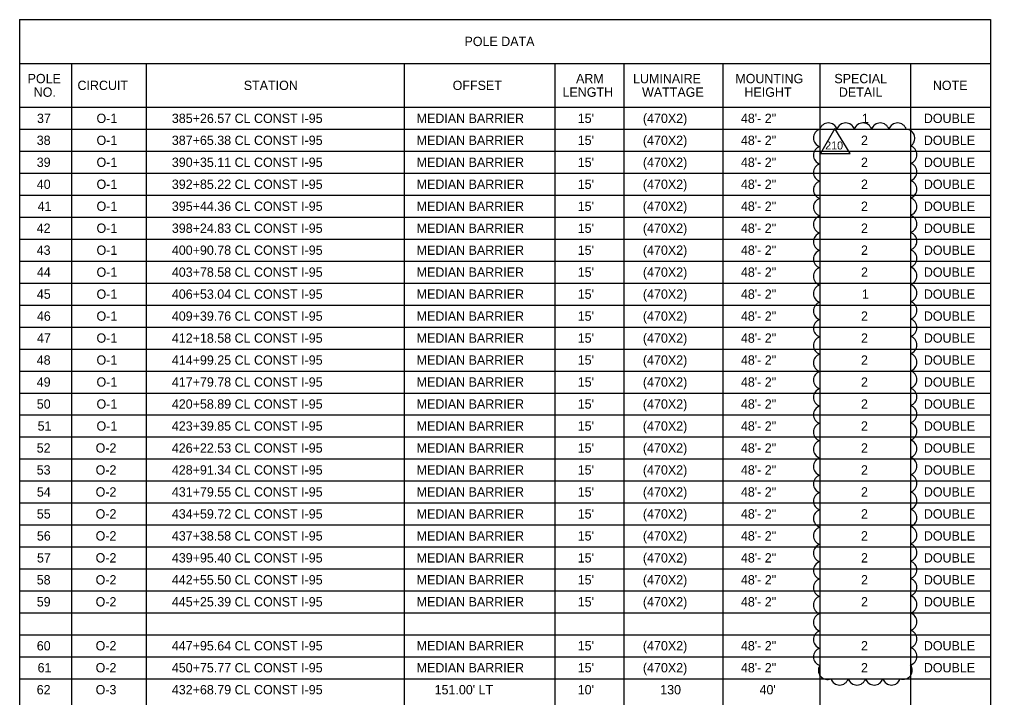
# Model space of a CAD drawing. Extents: x -816.7 to -727.6, y -2197.9 to -2187.8.
# Drawn here: x -808.11 to -800.82, y -2193.19 to -2188.1 of the extents above; entities that cross this region are included whole.
import ezdxf

# ---------------------------------------------------------------- set-up
doc = ezdxf.new("R2010")
doc.units = 0
for name, color, linetype in [('ClipBorder_dp', 7, 'Continuous'), ('MatchLines_dp', 7, 'Continuous'), ('NorthArw_dp', 7, 'Continuous'), ('PlotBorder_dp', 7, 'Continuous'), ('Scale_dp', 7, 'Continuous')]:
    doc.layers.add(name, color=color, linetype=linetype)

msp = doc.modelspace()

# ---------------------------------------------------------------- linework, layer by layer
at = {"layer": 'MatchLines_dp'}
for p, q in [((-808.1136, -2188.7573), (-807.1611, -2188.7573)), ((-804.0936, -2188.7573), (-800.8236, -2188.7573)), ((-808.1136, -2188.9223), (-807.1611, -2188.9223)), ((-808.1136, -2188.9223), (-800.8236, -2188.9223)), ((-805.2261, -2188.9223), (-800.8236, -2188.9223)), ((-808.1136, -2189.0873), (-800.8236, -2189.0873)), ((-808.1136, -2189.0873), (-800.8236, -2189.0873)), ((-808.1136, -2189.2523), (-800.8236, -2189.2523)), ((-808.1136, -2189.2523), (-800.8236, -2189.2523)), ((-808.1136, -2189.4173), (-800.8236, -2189.4173)), ((-808.1136, -2189.4173), (-800.8236, -2189.4173)), ((-808.1136, -2189.5823), (-800.8236, -2189.5823)), ((-808.1136, -2189.5823), (-800.8236, -2189.5823)), ((-808.1136, -2189.7473), (-800.8236, -2189.7473)), ((-808.1136, -2189.7473), (-800.8236, -2189.7473)), ((-808.1136, -2189.9123), (-800.8236, -2189.9123)), ((-808.1136, -2189.9123), (-800.8236, -2189.9123)), ((-808.1136, -2190.0773), (-800.8236, -2190.0773)), ((-808.1136, -2190.0773), (-800.8236, -2190.0773)), ((-808.1136, -2190.2423), (-800.8236, -2190.2423)), ((-808.1136, -2190.2423), (-800.8236, -2190.2423)), ((-808.1136, -2190.4073), (-800.8236, -2190.4073)), ((-808.1136, -2190.4073), (-800.8236, -2190.4073)), ((-808.1136, -2190.5723), (-807.1611, -2190.5723)), ((-808.1136, -2190.5723), (-800.8236, -2190.5723)), ((-804.0936, -2190.5723), (-800.8236, -2190.5723)), ((-808.1136, -2190.7373), (-807.7236, -2190.7373)), ((-808.1136, -2190.7373), (-800.8236, -2190.7373)), ((-807.1611, -2190.7373), (-805.2261, -2190.7373)), ((-803.5761, -2190.7373), (-802.1061, -2190.7373)), ((-808.1136, -2190.9023), (-800.8236, -2190.9023)), ((-808.1136, -2190.9023), (-800.8236, -2190.9023)), ((-808.1136, -2191.0673), (-807.7236, -2191.0673)), ((-808.1136, -2191.0673), (-800.8236, -2191.0673)), ((-802.8336, -2191.0673), (-802.1061, -2191.0673)), ((-808.1136, -2191.2323), (-807.7236, -2191.2323)), ((-808.1136, -2191.2323), (-800.8236, -2191.2323)), ((-802.8336, -2191.2323), (-802.1061, -2191.2323)), ((-808.1136, -2191.3973), (-800.8236, -2191.3973)), ((-808.1136, -2191.3973), (-800.8236, -2191.3973)), ((-808.1136, -2191.5623), (-800.8236, -2191.5623)), ((-808.1136, -2191.5623), (-800.8236, -2191.5623)), ((-808.1136, -2191.7273), (-800.8236, -2191.7273)), ((-808.1136, -2191.7273), (-800.8236, -2191.7273)), ((-808.1136, -2191.8923), (-800.8236, -2191.8923)), ((-808.1136, -2191.8923), (-800.8236, -2191.8923)), ((-808.1136, -2192.0573), (-800.8236, -2192.0573)), ((-808.1136, -2192.0573), (-800.8236, -2192.0573)), ((-808.1136, -2192.2223), (-800.8236, -2192.2223)), ((-808.1136, -2192.2223), (-800.8236, -2192.2223)), ((-808.1136, -2192.3873), (-800.8236, -2192.3873)), ((-808.1136, -2192.3873), (-800.8236, -2192.3873)), ((-808.1136, -2192.5523), (-800.8236, -2192.5523)), ((-808.1136, -2192.5523), (-800.8236, -2192.5523)), ((-808.1136, -2192.7173), (-800.8236, -2192.7173)), ((-808.1136, -2192.7173), (-800.8236, -2192.7173)), ((-808.1136, -2192.8823), (-800.8236, -2192.8823)), ((-808.1136, -2192.8823), (-800.8236, -2192.8823)), ((-808.1136, -2193.0473), (-800.8236, -2193.0473)), ((-808.1136, -2193.0473), (-800.8236, -2193.0473))]:
    msp.add_line(p, q, dxfattribs=at)
at = {"layer": 'NorthArw_dp'}
for p, q in [((-808.1136, -2188.0973), (-800.8236, -2188.0973)), ((-808.1136, -2188.0973), (-808.1136, -2194.6973)), ((-800.8236, -2188.0973), (-800.8236, -2194.6973)), ((-808.1136, -2188.4273), (-800.8236, -2188.4273)), ((-808.1136, -2188.4273), (-800.8236, -2188.4273))]:
    msp.add_line(p, q, dxfattribs=at)
at = {"layer": 'PlotBorder_dp'}
msp.add_lwpolyline([(-801.9916, -2188.9159), (-802.0993, -2189.1039), (-801.8787, -2189.1039)], close=True, dxfattribs=at)
for centre, radius, start, end in [((-802.0411, -2188.9427), 0.0681, 17.5, 162.5), ((-801.9113, -2188.9427), 0.0681, 17.5, 162.5), ((-801.7814, -2188.9427), 0.0681, 17.5, 162.5), ((-801.6515, -2188.9427), 0.0681, 17.5, 162.5), ((-801.5216, -2188.9427), 0.0681, 17.5, 162.5), ((-802.0856, -2188.9872), 0.0681, 107.5, 252.5), ((-801.4599, -2188.9903), 0.0681, 302.28004, 87.28004), ((-802.0856, -2189.1171), 0.0681, 107.5, 252.5), ((-801.4441, -2189.1128), 0.0681, 287.5, 72.5), ((-802.0856, -2189.2469), 0.0681, 107.5, 252.5), ((-801.4441, -2189.2426), 0.0681, 287.5, 72.5), ((-802.0856, -2189.3768), 0.0681, 107.5, 252.5), ((-801.4441, -2189.3725), 0.0681, 287.5, 72.5), ((-802.0856, -2189.5067), 0.0681, 107.5, 252.5), ((-801.4441, -2189.5024), 0.0681, 287.5, 72.5), ((-802.0856, -2189.6366), 0.0681, 107.5, 252.5), ((-801.4441, -2189.6323), 0.0681, 287.5, 72.5), ((-801.4441, -2189.7621), 0.0681, 287.5, 72.5), ((-802.0856, -2189.7664), 0.0681, 107.5, 252.5), ((-802.0856, -2189.8963), 0.0681, 107.5, 252.5), ((-801.4441, -2189.892), 0.0681, 287.5, 72.5), ((-802.0856, -2190.0262), 0.0681, 107.5, 252.5), ((-801.4441, -2190.0219), 0.0681, 287.5, 72.5), ((-802.0856, -2190.1561), 0.0681, 107.5, 252.5), ((-801.4441, -2190.1518), 0.0681, 287.5, 72.5), ((-802.0856, -2190.2859), 0.0681, 107.5, 252.5), ((-801.4441, -2190.2816), 0.0681, 287.5, 72.5), ((-802.0856, -2190.4158), 0.0681, 107.5, 252.5), ((-801.4441, -2190.4115), 0.0681, 287.5, 72.5), ((-802.0856, -2190.5457), 0.0681, 107.5, 252.5), ((-801.4441, -2190.5414), 0.0681, 287.5, 72.5), ((-802.0856, -2190.6756), 0.0681, 107.5, 252.5), ((-801.4441, -2190.6713), 0.0681, 287.5, 72.5), ((-802.0856, -2190.8054), 0.0681, 107.5, 252.5), ((-801.4441, -2190.8011), 0.0681, 287.5, 72.5), ((-802.0856, -2190.9353), 0.0681, 107.5, 252.5), ((-801.4441, -2190.931), 0.0681, 287.5, 72.5), ((-802.0856, -2191.0652), 0.0681, 107.5, 252.5), ((-801.4441, -2191.0609), 0.0681, 287.5, 72.5), ((-802.0856, -2191.1951), 0.0681, 107.5, 252.5), ((-801.4441, -2191.1908), 0.0681, 287.5, 72.5), ((-802.0856, -2191.3249), 0.0681, 107.5, 252.5), ((-801.4441, -2191.3206), 0.0681, 287.5, 72.5), ((-802.0856, -2191.4548), 0.0681, 107.5, 252.5), ((-801.4441, -2191.4505), 0.0681, 287.5, 72.5), ((-802.0856, -2191.5847), 0.0681, 107.5, 252.5), ((-801.4441, -2191.5804), 0.0681, 287.5, 72.5), ((-802.0856, -2191.7146), 0.0681, 107.5, 252.5), ((-801.4441, -2191.7103), 0.0681, 287.5, 72.5), ((-802.0856, -2191.8444), 0.0681, 107.5, 252.5), ((-801.4441, -2191.8401), 0.0681, 287.5, 72.5), ((-802.0856, -2191.9743), 0.0681, 107.5, 252.5), ((-801.4441, -2191.97), 0.0681, 287.5, 72.5), ((-802.0856, -2192.1042), 0.0681, 107.5, 252.5), ((-801.4441, -2192.0999), 0.0681, 287.5, 72.5), ((-802.0856, -2192.2341), 0.0681, 107.5, 252.5), ((-801.4441, -2192.2297), 0.0681, 287.5, 72.5), ((-802.0856, -2192.3639), 0.0681, 107.5, 252.5), ((-801.4441, -2192.3596), 0.0681, 287.5, 72.5), ((-802.0856, -2192.4938), 0.0681, 107.5, 252.5), ((-801.4441, -2192.4895), 0.0681, 287.5, 72.5), ((-802.0856, -2192.6237), 0.0681, 107.5, 252.5), ((-801.4441, -2192.6194), 0.0681, 287.5, 72.5), ((-801.4441, -2192.7492), 0.0681, 287.5, 72.5), ((-802.0856, -2192.7536), 0.0681, 107.5, 252.5), ((-802.0856, -2192.8834), 0.0681, 107.5, 252.5), ((-801.4441, -2192.8791), 0.0681, 287.5, 72.5), ((-802.0483, -2192.9845), 0.0682, 147.97751, 292.97751), ((-801.4792, -2192.9833), 0.068, 250.17665, 35.17665), ((-801.9568, -2193.0268), 0.0681, 197.5, 342.5), ((-801.8269, -2193.0268), 0.0681, 197.5, 342.5), ((-801.6971, -2193.0268), 0.0681, 197.5, 342.5), ((-801.5672, -2193.0268), 0.0681, 197.5, 342.5)]:
    msp.add_arc(centre, radius, start, end, dxfattribs=at)
at = {"layer": 'Scale_dp'}
for p, q in [((-807.7236, -2188.4273), (-807.7236, -2194.6973)), ((-807.7236, -2188.4273), (-807.7236, -2194.6973)), ((-807.1611, -2188.4273), (-807.1611, -2194.6973)), ((-807.1611, -2188.4273), (-807.1611, -2194.6973)), ((-805.2261, -2188.4273), (-805.2261, -2188.7573)), ((-805.2261, -2188.4273), (-805.2261, -2194.6973)), ((-804.0936, -2188.4273), (-804.0936, -2194.5323)), ((-804.0936, -2188.4273), (-804.0936, -2194.6973)), ((-803.5761, -2188.4273), (-803.5761, -2194.5323)), ((-803.5761, -2188.4273), (-803.5761, -2194.6973)), ((-802.8336, -2188.4273), (-802.8336, -2194.6973)), ((-802.8336, -2188.4273), (-802.8336, -2194.6973)), ((-802.1061, -2188.4273), (-802.1061, -2194.6973)), ((-802.1061, -2188.4273), (-802.1061, -2194.6973)), ((-801.4236, -2188.4273), (-801.4236, -2194.6973)), ((-808.1136, -2188.7573), (-800.8236, -2188.7573)), ((-807.1611, -2188.7573), (-804.0936, -2188.7573)), ((-805.2261, -2188.9223), (-805.2261, -2194.6973))]:
    msp.add_line(p, q, dxfattribs=at)

# ---------------------------------------------------------------- texts
at = {"layer": 'ClipBorder_dp'}
for s, p in [('POLE DATA', (-804.7725, -2188.2973)), ('POLE', (-808.0519, -2188.5763)), ('ARM', (-803.9353, -2188.5763)), ('LUMINAIRE', (-803.5075, -2188.5763)), ('MOUNTING', (-802.7395, -2188.5763)), ('SPECIAL', (-801.9962, -2188.5763)), ('CIRCUIT', (-807.6777, -2188.6273)), ('STATION', (-806.4294, -2188.6273)), ('OFFSET', (-804.8613, -2188.6273)), ('NOTE', (-801.2569, -2188.6273)), ('NO.', (-808.0062, -2188.6783)), ('LENGTH', (-804.0368, -2188.6783)), ('WATTAGE', (-803.4397, -2188.6783)), ('HEIGHT', (-802.6713, -2188.6783)), ('DETAIL', (-801.9624, -2188.6783)), ('37', (-807.9819, -2188.8748)), ('O-1', (-807.5348, -2188.8748)), ('385+26.57 CL CONST I-95', (-806.9694, -2188.8748)), ('MEDIAN BARRIER', (-805.1319, -2188.8748)), ("15'", (-803.9228, -2188.8748)), ('(470X2)', (-803.4333, -2188.8748)), ('48\'- 2"', (-802.6977, -2188.8748)), ('1', (-801.7895, -2188.8748)), ('DOUBLE', (-801.3246, -2188.8748)), ('(470X2)', (-803.4333, -2189.0398)), ('38', (-807.9836, -2189.0398)), ('O-1', (-807.5348, -2189.0398)), ('387+65.38 CL CONST I-95', (-806.9694, -2189.0398)), ('MEDIAN BARRIER', (-805.1319, -2189.0398)), ("15'", (-803.9228, -2189.0398)), ('48\'- 2"', (-802.6977, -2189.0398)), ('2', (-801.7962, -2189.0398)), ('DOUBLE', (-801.3246, -2189.0398)), ('39', (-807.9835, -2189.2048)), ('O-1', (-807.5348, -2189.2048)), ('390+35.11 CL CONST I-95', (-806.9694, -2189.2048)), ('MEDIAN BARRIER', (-805.1319, -2189.2048)), ("15'", (-803.9228, -2189.2048)), ('(470X2)', (-803.4333, -2189.2048)), ('48\'- 2"', (-802.6977, -2189.2048)), ('2', (-801.7962, -2189.2048)), ('DOUBLE', (-801.3246, -2189.2048)), ('40', (-807.9833, -2189.3698)), ('O-1', (-807.5348, -2189.3698)), ('392+85.22 CL CONST I-95', (-806.9694, -2189.3698)), ('MEDIAN BARRIER', (-805.1319, -2189.3698)), ("15'", (-803.9228, -2189.3698)), ('(470X2)', (-803.4333, -2189.3698)), ('48\'- 2"', (-802.6977, -2189.3698)), ('2', (-801.7962, -2189.3698)), ('DOUBLE', (-801.3246, -2189.3698)), ('41', (-807.9771, -2189.5348)), ('O-1', (-807.5348, -2189.5348)), ('395+44.36 CL CONST I-95', (-806.9694, -2189.5348)), ('MEDIAN BARRIER', (-805.1319, -2189.5348)), ("15'", (-803.9228, -2189.5348)), ('(470X2)', (-803.4333, -2189.5348)), ('48\'- 2"', (-802.6977, -2189.5348)), ('2', (-801.7962, -2189.5348)), ('DOUBLE', (-801.3246, -2189.5348)), ('42', (-807.9839, -2189.6998)), ('O-1', (-807.5348, -2189.6998)), ('398+24.83 CL CONST I-95', (-806.9694, -2189.6998)), ('MEDIAN BARRIER', (-805.1319, -2189.6998)), ("15'", (-803.9228, -2189.6998)), ('(470X2)', (-803.4333, -2189.6998)), ('48\'- 2"', (-802.6977, -2189.6998)), ('2', (-801.7962, -2189.6998)), ('DOUBLE', (-801.3246, -2189.6998)), ('43', (-807.9839, -2189.8648)), ('O-1', (-807.5348, -2189.8648)), ('400+90.78 CL CONST I-95', (-806.9694, -2189.8648)), ('MEDIAN BARRIER', (-805.1319, -2189.8648)), ("15'", (-803.9228, -2189.8648)), ('(470X2)', (-803.4333, -2189.8648)), ('48\'- 2"', (-802.6977, -2189.8648)), ('2', (-801.7962, -2189.8648)), ('DOUBLE', (-801.3246, -2189.8648)), ('44', (-807.9825, -2190.0298)), ('O-1', (-807.5348, -2190.0298)), ('403+78.58 CL CONST I-95', (-806.9694, -2190.0298)), ('MEDIAN BARRIER', (-805.1319, -2190.0298)), ("15'", (-803.9228, -2190.0298)), ('(470X2)', (-803.4333, -2190.0298)), ('48\'- 2"', (-802.6977, -2190.0298)), ('2', (-801.7962, -2190.0298)), ('DOUBLE', (-801.3246, -2190.0298)), ('45', (-807.983, -2190.1948)), ('O-1', (-807.5348, -2190.1948)), ('406+53.04 CL CONST I-95', (-806.9694, -2190.1948)), ('MEDIAN BARRIER', (-805.1319, -2190.1948)), ("15'", (-803.9228, -2190.1948)), ('(470X2)', (-803.4333, -2190.1948)), ('48\'- 2"', (-802.6977, -2190.1948)), ('1', (-801.7895, -2190.1948)), ('DOUBLE', (-801.3246, -2190.1948)), ('46', (-807.9825, -2190.3598)), ('O-1', (-807.5348, -2190.3598)), ('409+39.76 CL CONST I-95', (-806.9694, -2190.3598)), ('MEDIAN BARRIER', (-805.1319, -2190.3598)), ("15'", (-803.9228, -2190.3598)), ('(470X2)', (-803.4333, -2190.3598)), ('48\'- 2"', (-802.6977, -2190.3598)), ('2', (-801.7962, -2190.3598)), ('DOUBLE', (-801.3246, -2190.3598)), ('47', (-807.9819, -2190.5248)), ('O-1', (-807.5348, -2190.5248)), ('412+18.58 CL CONST I-95', (-806.9694, -2190.5248)), ('MEDIAN BARRIER', (-805.1319, -2190.5248)), ("15'", (-803.9228, -2190.5248)), ('(470X2)', (-803.4333, -2190.5248)), ('48\'- 2"', (-802.6977, -2190.5248)), ('2', (-801.7962, -2190.5248)), ('DOUBLE', (-801.3246, -2190.5248)), ('48', (-807.9836, -2190.6898)), ('O-1', (-807.5348, -2190.6898)), ('414+99.25 CL CONST I-95', (-806.9694, -2190.6898)), ('MEDIAN BARRIER', (-805.1319, -2190.6898)), ("15'", (-803.9228, -2190.6898)), ('(470X2)', (-803.4333, -2190.6898)), ('48\'- 2"', (-802.6977, -2190.6898)), ('2', (-801.7962, -2190.6898)), ('DOUBLE', (-801.3246, -2190.6898)), ('49', (-807.9835, -2190.8548)), ('O-1', (-807.5348, -2190.8548)), ('417+79.78 CL CONST I-95', (-806.9694, -2190.8548)), ('MEDIAN BARRIER', (-805.1319, -2190.8548)), ("15'", (-803.9228, -2190.8548)), ('(470X2)', (-803.4333, -2190.8548)), ('48\'- 2"', (-802.6977, -2190.8548)), ('2', (-801.7962, -2190.8548)), ('DOUBLE', (-801.3246, -2190.8548)), ('50', (-807.9833, -2191.0198)), ('O-1', (-807.5348, -2191.0198)), ('420+58.89 CL CONST I-95', (-806.9694, -2191.0198)), ('MEDIAN BARRIER', (-805.1319, -2191.0198)), ("15'", (-803.9228, -2191.0198)), ('(470X2)', (-803.4333, -2191.0198)), ('48\'- 2"', (-802.6977, -2191.0198)), ('2', (-801.7962, -2191.0198)), ('DOUBLE', (-801.3246, -2191.0198)), ('51', (-807.9771, -2191.1848)), ('O-1', (-807.5348, -2191.1848)), ('423+39.85 CL CONST I-95', (-806.9694, -2191.1848)), ('MEDIAN BARRIER', (-805.1319, -2191.1848)), ("15'", (-803.9228, -2191.1848)), ('(470X2)', (-803.4333, -2191.1848)), ('48\'- 2"', (-802.6977, -2191.1848)), ('2', (-801.7962, -2191.1848)), ('DOUBLE', (-801.3246, -2191.1848)), ('52', (-807.9839, -2191.3498)), ('O-2', (-807.5415, -2191.3498)), ('426+22.53 CL CONST I-95', (-806.9694, -2191.3498)), ('MEDIAN BARRIER', (-805.1319, -2191.3498)), ("15'", (-803.9228, -2191.3498)), ('(470X2)', (-803.4333, -2191.3498)), ('48\'- 2"', (-802.6977, -2191.3498)), ('2', (-801.7962, -2191.3498)), ('DOUBLE', (-801.3246, -2191.3498)), ('53', (-807.9839, -2191.5148)), ('O-2', (-807.5415, -2191.5148)), ('428+91.34 CL CONST I-95', (-806.9694, -2191.5148)), ('MEDIAN BARRIER', (-805.1319, -2191.5148)), ("15'", (-803.9228, -2191.5148)), ('(470X2)', (-803.4333, -2191.5148)), ('48\'- 2"', (-802.6977, -2191.5148)), ('2', (-801.7962, -2191.5148)), ('DOUBLE', (-801.3246, -2191.5148)), ('54', (-807.9825, -2191.6798)), ('O-2', (-807.5415, -2191.6798)), ('431+79.55 CL CONST I-95', (-806.9694, -2191.6798)), ('MEDIAN BARRIER', (-805.1319, -2191.6798)), ("15'", (-803.9228, -2191.6798)), ('(470X2)', (-803.4333, -2191.6798)), ('48\'- 2"', (-802.6977, -2191.6798)), ('2', (-801.7962, -2191.6798)), ('DOUBLE', (-801.3246, -2191.6798)), ('55', (-807.983, -2191.8448)), ('O-2', (-807.5415, -2191.8448)), ('434+59.72 CL CONST I-95', (-806.9694, -2191.8448)), ('MEDIAN BARRIER', (-805.1319, -2191.8448)), ("15'", (-803.9228, -2191.8448)), ('(470X2)', (-803.4333, -2191.8448)), ('48\'- 2"', (-802.6977, -2191.8448)), ('2', (-801.7962, -2191.8448)), ('DOUBLE', (-801.3246, -2191.8448)), ('56', (-807.9825, -2192.0098)), ('O-2', (-807.5415, -2192.0098)), ('437+38.58 CL CONST I-95', (-806.9694, -2192.0098)), ('MEDIAN BARRIER', (-805.1319, -2192.0098)), ("15'", (-803.9228, -2192.0098)), ('(470X2)', (-803.4333, -2192.0098)), ('48\'- 2"', (-802.6977, -2192.0098)), ('2', (-801.7962, -2192.0098)), ('DOUBLE', (-801.3246, -2192.0098)), ('(470X2)', (-803.4333, -2192.1748)), ('57', (-807.9819, -2192.1748)), ('O-2', (-807.5415, -2192.1748)), ('439+95.40 CL CONST I-95', (-806.9694, -2192.1748)), ('MEDIAN BARRIER', (-805.1319, -2192.1748)), ("15'", (-803.9228, -2192.1748)), ('48\'- 2"', (-802.6977, -2192.1748)), ('2', (-801.7962, -2192.1748)), ('DOUBLE', (-801.3246, -2192.1748)), ('58', (-807.9836, -2192.3398)), ('O-2', (-807.5415, -2192.3398)), ('442+55.50 CL CONST I-95', (-806.9694, -2192.3398)), ('MEDIAN BARRIER', (-805.1319, -2192.3398)), ("15'", (-803.9228, -2192.3398)), ('(470X2)', (-803.4333, -2192.3398)), ('48\'- 2"', (-802.6977, -2192.3398)), ('2', (-801.7962, -2192.3398)), ('DOUBLE', (-801.3246, -2192.3398)), ('59', (-807.9835, -2192.5048)), ('O-2', (-807.5415, -2192.5048)), ('445+25.39 CL CONST I-95', (-806.9694, -2192.5048)), ('MEDIAN BARRIER', (-805.1319, -2192.5048)), ("15'", (-803.9228, -2192.5048)), ('(470X2)', (-803.4333, -2192.5048)), ('48\'- 2"', (-802.6977, -2192.5048)), ('2', (-801.7962, -2192.5048)), ('DOUBLE', (-801.3246, -2192.5048)), ('60', (-807.9833, -2192.8348)), ('O-2', (-807.5415, -2192.8348)), ('447+95.64 CL CONST I-95', (-806.9694, -2192.8348)), ('MEDIAN BARRIER', (-805.1319, -2192.8348)), ("15'", (-803.9228, -2192.8348)), ('(470X2)', (-803.4333, -2192.8348)), ('48\'- 2"', (-802.6977, -2192.8348)), ('2', (-801.7962, -2192.8348)), ('DOUBLE', (-801.3246, -2192.8348)), ('61', (-807.9771, -2192.9998)), ('O-2', (-807.5415, -2192.9998)), ('450+75.77 CL CONST I-95', (-806.9694, -2192.9998)), ('MEDIAN BARRIER', (-805.1319, -2192.9998)), ("15'", (-803.9228, -2192.9998)), ('(470X2)', (-803.4333, -2192.9998)), ('48\'- 2"', (-802.6977, -2192.9998)), ('2', (-801.7962, -2192.9998)), ('DOUBLE', (-801.3246, -2192.9998)), ('62', (-807.9839, -2193.1648)), ('O-3', (-807.5415, -2193.1648)), ('432+68.79 CL CONST I-95', (-806.9694, -2193.1648)), ("151.00' LT", (-804.9968, -2193.1648)), ("10'", (-803.9228, -2193.1648)), ('130', (-803.3034, -2193.1648)), ("40'", (-802.5578, -2193.1648))]:
    msp.add_text(s, height=0.07, dxfattribs=at).set_placement(p)
at = {"layer": 'PlotBorder_dp'}
msp.add_text('210', height=0.05998, rotation=0, dxfattribs=at).set_placement((-802.0648, -2189.0738))

doc.saveas('drawing.dxf')
